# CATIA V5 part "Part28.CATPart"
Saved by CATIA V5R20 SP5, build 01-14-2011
Part number: Part28
Material "Water": density 1000 kg/m3
Bounding box of the stored display mesh (mm): x -1.919 to 1.919, y -2 to 2, z -1.919 to 1.919
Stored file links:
  D:\新建文件夹\Part28.CATPart
  C:\Program Files\Dassault Systemes\B20\intel_a\startup\materials\Catalog.CATMaterial
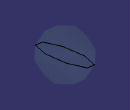
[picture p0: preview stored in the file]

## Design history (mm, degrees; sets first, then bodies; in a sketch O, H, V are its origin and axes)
Body1 (main body), material "Water"
  Sketch1 on xy-plane, origin (0, 0, 0), H (1, 0, 0), V (0, 1, 0)
    arc A1 centre (0, 0) radius 2 from (0, -2) to (0, 2) ccw
    axis line L1 (0, 2.6954) -> (0, -2.923)
    point P1 (0, 2.6954)
    point P3 (0, 2)
    point P4 (0, -2)
    radius A1 = 2
    coincidence: P1 V, L1 P3, L1 P4
    vertical: L1 V
  Shaft1: profile Sketch1, axis Sketch1.L1, angle 360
